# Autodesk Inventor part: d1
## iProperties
Created: 2002-02
Part Number: d1
Document SubType Name: ﾓﾃﾞﾘﾝｸﾞ
Designer: Administrator
Control State: 0
Master: False
Checked Out: False
Shininess: 77.0
Length Units: 11269
Angle Units: 11279
Time Units: 11290
Mass Units: 11284
Length Display Precision: 2
Angle Display Precision: 1
Density: 0.0
Volumn: 0.0
Area: 0.0
PropertySet Name: Model Information
Author: Administrator
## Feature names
1. 押し出し1 [Extrusion]
2. 押し出し2 [Extrusion]
3. 押し出し3 [Extrusion]
4. 押し出し4 [Extrusion]
